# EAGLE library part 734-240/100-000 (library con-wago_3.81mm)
Serie 734, Stiftleiste (für Leiterplatten) Einpressstift 0,6 x 0,6 mm / Series 734, Male header (for PCBs) Press-in pin 0.6 x 0.6 mm Polzahl / Pole No.: 10 Rastermaß / Pitch: 3.81 mm Bemessungsspannung / Rated Voltage: 160 V Nennstrom / Nominal Current: 8 A Farbe / Color: orange / orange Stand: 01.01.2012. Die jeweils aktuellen Daten zu diesem Artikel finden Sie in unserem Produktkatalog, den Sie unter www.wago.com einsehen können. As of: 01/01/2012. Please find the newest data for this article in our product catalogue, which can be viewed under www.wago.com.
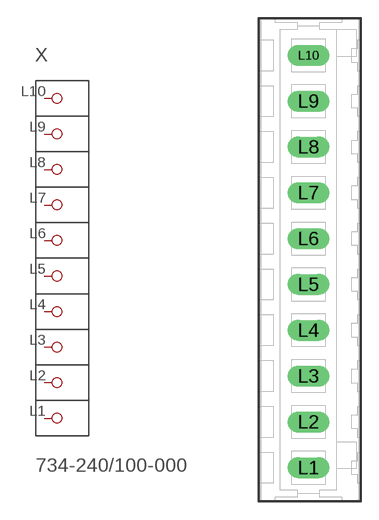
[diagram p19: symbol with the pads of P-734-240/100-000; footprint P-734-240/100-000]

Designator prefix X

## 734-240/100-000  [P-734-240/100-000]
L1  P1.1
L2  P2
L3  P3
L4  P4
L5  P5
L6  P6
L7  P7
L8  P8
L9  P9
L10  P10

## Footprint P-734-240/100-000 (pad centres in mm)
drill 1.15 long: L1 -0.1,-17.295; L2 -0.1,-13.485; L3 -0.1,-9.675; L4 -0.1,-5.865; L5 -0.1,-2.055; L6 -0.1,1.755; L7 -0.1,5.565; L8 -0.1,9.375; L9 -0.1,13.185; L10 -0.1,16.995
